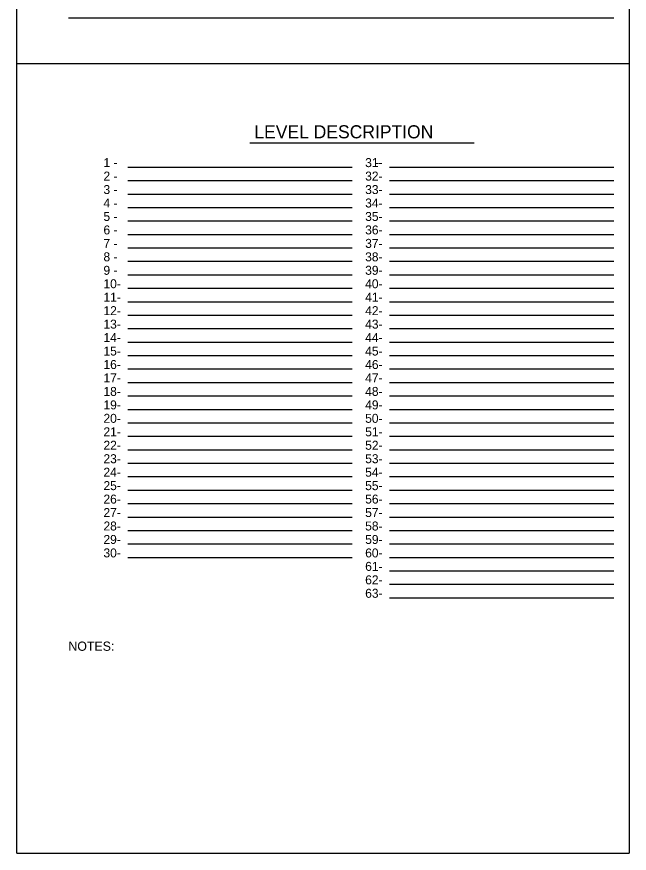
# Model space of a CAD drawing. Extents: x 10040.55 to 10045.84, y 10033.26 to 10035.76.
# Drawn here: x 10044.121 to 10044.832, y 10033.283 to 10034.254 of the extents above; entities that cross this region are included whole.
import ezdxf

# ---------------------------------------------------------------- set-up
doc = ezdxf.new("R2010")
doc.units = 0
doc.layers.add('Level 8', color=7, linetype='Continuous')

msp = doc.modelspace()

# ---------------------------------------------------------------- linework, layer by layer
at = {"layer": 'Level 8'}
for p, q in [((10044.12093, 10033.28296), (10044.12093, 10035.11629)), ((10044.83201, 10035.11629), (10044.83201, 10033.28296)), ((10044.81399, 10034.25256), (10044.18091, 10034.25256)), ((10044.83201, 10034.19963), (10044.12093, 10034.19963)), ((10044.39145, 10034.10792), (10044.65188, 10034.10792)), ((10044.24975, 10034.07957), (10044.51017, 10034.07957)), ((10044.55356, 10034.07957), (10044.81399, 10034.07957)), ((10044.24975, 10034.06395), (10044.51017, 10034.06395)), ((10044.55356, 10034.06395), (10044.81399, 10034.06395)), ((10044.24975, 10034.04832), (10044.51017, 10034.04832)), ((10044.55356, 10034.04832), (10044.81399, 10034.04832)), ((10044.24975, 10034.0327), (10044.51017, 10034.0327)), ((10044.55356, 10034.0327), (10044.81399, 10034.0327)), ((10044.24975, 10034.01707), (10044.51017, 10034.01707)), ((10044.55356, 10034.01707), (10044.81399, 10034.01707)), ((10044.24975, 10034.00145), (10044.51017, 10034.00145)), ((10044.55356, 10034.00145), (10044.81399, 10034.00145)), ((10044.24975, 10033.98582), (10044.51017, 10033.98582)), ((10044.55356, 10033.98582), (10044.81399, 10033.98582)), ((10044.24975, 10033.9702), (10044.51017, 10033.9702)), ((10044.55356, 10033.9702), (10044.81399, 10033.9702)), ((10044.24975, 10033.95457), (10044.51017, 10033.95457)), ((10044.55356, 10033.95457), (10044.81399, 10033.95457)), ((10044.24975, 10033.93895), (10044.51017, 10033.93895)), ((10044.55356, 10033.93895), (10044.81399, 10033.93895)), ((10044.24975, 10033.92332), (10044.51017, 10033.92332)), ((10044.55356, 10033.92332), (10044.81399, 10033.92332)), ((10044.24975, 10033.9077), (10044.51017, 10033.9077)), ((10044.55356, 10033.9077), (10044.81399, 10033.9077)), ((10044.24975, 10033.89207), (10044.51017, 10033.89207)), ((10044.55356, 10033.89207), (10044.81399, 10033.89207)), ((10044.24975, 10033.87645), (10044.51017, 10033.87645)), ((10044.55356, 10033.87645), (10044.81399, 10033.87645)), ((10044.24975, 10033.86082), (10044.51017, 10033.86082)), ((10044.55356, 10033.86082), (10044.81399, 10033.86082)), ((10044.24975, 10033.8452), (10044.51017, 10033.8452)), ((10044.55356, 10033.8452), (10044.81399, 10033.8452)), ((10044.24975, 10033.82957), (10044.51017, 10033.82957)), ((10044.55356, 10033.82957), (10044.81399, 10033.82957)), ((10044.24975, 10033.81395), (10044.51017, 10033.81395)), ((10044.55356, 10033.81395), (10044.81399, 10033.81395)), ((10044.24975, 10033.79832), (10044.51017, 10033.79832)), ((10044.55356, 10033.79832), (10044.81399, 10033.79832)), ((10044.24975, 10033.7827), (10044.51017, 10033.7827)), ((10044.55356, 10033.7827), (10044.81399, 10033.7827)), ((10044.24975, 10033.76707), (10044.51017, 10033.76707)), ((10044.55356, 10033.76707), (10044.81399, 10033.76707)), ((10044.24975, 10033.75145), (10044.51017, 10033.75145)), ((10044.55356, 10033.75145), (10044.81399, 10033.75145)), ((10044.24975, 10033.73582), (10044.51017, 10033.73582)), ((10044.55356, 10033.73582), (10044.81399, 10033.73582)), ((10044.24975, 10033.7202), (10044.51017, 10033.7202)), ((10044.55356, 10033.7202), (10044.81399, 10033.7202)), ((10044.24975, 10033.70457), (10044.51017, 10033.70457)), ((10044.55356, 10033.70457), (10044.81399, 10033.70457)), ((10044.24975, 10033.68895), (10044.51017, 10033.68895)), ((10044.55356, 10033.68895), (10044.81399, 10033.68895)), ((10044.24975, 10033.67332), (10044.51017, 10033.67332)), ((10044.55356, 10033.67332), (10044.81399, 10033.67332)), ((10044.24975, 10033.6577), (10044.51017, 10033.6577)), ((10044.55356, 10033.6577), (10044.81399, 10033.6577)), ((10044.24975, 10033.64207), (10044.51017, 10033.64207)), ((10044.55356, 10033.64207), (10044.81399, 10033.64207)), ((10044.24975, 10033.62645), (10044.51017, 10033.62645)), ((10044.55356, 10033.62645), (10044.81399, 10033.62645)), ((10044.55356, 10033.61082), (10044.81399, 10033.61082)), ((10044.55356, 10033.5952), (10044.81399, 10033.5952)), ((10044.55356, 10033.57957), (10044.81399, 10033.57957)), ((10044.12093, 10033.28296), (10044.83201, 10033.28296))]:
    msp.add_line(p, q, dxfattribs=at)

# ---------------------------------------------------------------- texts
for s, height, p in [('LEVEL DESCRIPTION', 0.0151914, (10044.39679, 10034.11299)), ('1 -', 0.010417, (10044.22161, 10034.07957)), ('31-', 0.010417, (10044.52544, 10034.07957)), ('3 -', 0.010417, (10044.52544, 10034.07957)), ('2 -', 0.010417, (10044.22161, 10034.06395)), ('32-', 0.010417, (10044.52544, 10034.06395)), ('3 -', 0.010417, (10044.22161, 10034.04832)), ('33-', 0.010417, (10044.52544, 10034.04832)), ('4 -', 0.010417, (10044.22161, 10034.0327)), ('34-', 0.010417, (10044.52544, 10034.0327)), ('5 -', 0.010417, (10044.22161, 10034.01707)), ('35-', 0.010417, (10044.52544, 10034.01707)), ('6 -', 0.010417, (10044.22161, 10034.00145)), ('36-', 0.010417, (10044.52544, 10034.00145)), ('7 -', 0.010417, (10044.22161, 10033.98582)), ('37-', 0.010417, (10044.52544, 10033.98582)), ('8 -', 0.010417, (10044.22161, 10033.9702)), ('38-', 0.010417, (10044.52544, 10033.9702)), ('9 -', 0.010417, (10044.22161, 10033.95457)), ('39-', 0.010417, (10044.52544, 10033.95457)), ('10-', 0.010417, (10044.22161, 10033.93895)), ('40-', 0.010417, (10044.52544, 10033.93895)), ('11-', 0.010417, (10044.22161, 10033.92332)), ('41-', 0.010417, (10044.52544, 10033.92332)), ('12-', 0.010417, (10044.22161, 10033.9077)), ('42-', 0.010417, (10044.52544, 10033.9077)), ('13-', 0.010417, (10044.22161, 10033.89207)), ('43-', 0.010417, (10044.52544, 10033.89207)), ('14-', 0.010417, (10044.22161, 10033.87645)), ('44-', 0.010417, (10044.52544, 10033.87645)), ('15-', 0.010417, (10044.22161, 10033.86082)), ('45-', 0.010417, (10044.52544, 10033.86082)), ('16-', 0.010417, (10044.22161, 10033.8452)), ('46-', 0.010417, (10044.52544, 10033.8452)), ('17-', 0.010417, (10044.22161, 10033.82957)), ('47-', 0.010417, (10044.52544, 10033.82957)), ('18-', 0.010417, (10044.22161, 10033.81395)), ('48-', 0.010417, (10044.52544, 10033.81395)), ('19-', 0.010417, (10044.22161, 10033.79832)), ('49-', 0.010417, (10044.52544, 10033.79832)), ('20-', 0.010417, (10044.22161, 10033.7827)), ('50-', 0.010417, (10044.52544, 10033.7827)), ('21-', 0.010417, (10044.22161, 10033.76707)), ('51-', 0.010417, (10044.52544, 10033.76707)), ('22-', 0.010417, (10044.22161, 10033.75145)), ('52-', 0.010417, (10044.52544, 10033.75145)), ('23-', 0.010417, (10044.22161, 10033.73582)), ('53-', 0.010417, (10044.52544, 10033.73582)), ('24-', 0.010416, (10044.22161, 10033.7202)), ('54-', 0.010416, (10044.52544, 10033.7202)), ('25-', 0.010417, (10044.22161, 10033.70457)), ('55-', 0.010417, (10044.52544, 10033.70457)), ('26-', 0.010417, (10044.22161, 10033.68895)), ('56-', 0.010417, (10044.52544, 10033.68895)), ('27-', 0.010417, (10044.22161, 10033.67332)), ('57-', 0.010417, (10044.52544, 10033.67332)), ('28-', 0.010417, (10044.22161, 10033.6577)), ('58-', 0.010417, (10044.52544, 10033.6577)), ('29-', 0.010417, (10044.22161, 10033.64207)), ('59-', 0.010417, (10044.52544, 10033.64207)), ('30-', 0.010417, (10044.22161, 10033.62645)), ('60-', 0.010417, (10044.52544, 10033.62645)), ('61-', 0.010417, (10044.52544, 10033.61082)), ('62-', 0.010417, (10044.52544, 10033.5952)), ('63-', 0.010417, (10044.52544, 10033.57957)), ('NOTES:', 0.010717, (10044.18091, 10033.51802))]:
    msp.add_text(s, height=height, dxfattribs=at).set_placement(p)

doc.saveas('drawing.dxf')
